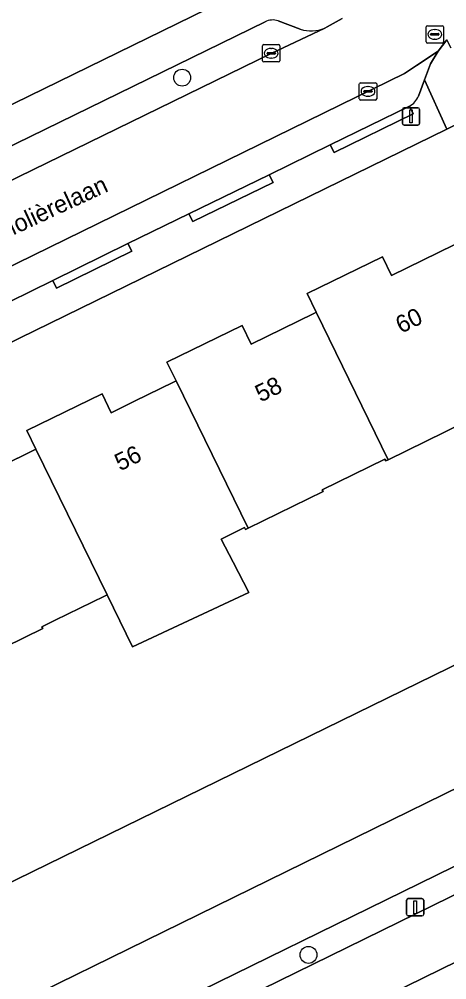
# Model space of a CAD drawing. Extents: x 160455 to 162082, y 388339 to 389736.
# Drawn here: x 160904.5 to 160929.1, y 388725.9 to 388781.3 of the extents above; entities that cross this region are included whole.
import ezdxf

# ---------------------------------------------------------------- set-up
doc = ezdxf.new("R2010")
doc.units = 0
for name, color, linetype in [('IMGEO_Boom', 7, 'Continuous'), ('IMGEO_Erf', 7, 'Continuous'), ('IMGEO_Fietspad_gesloten', 7, 'Continuous'), ('IMGEO_Groenvoorziening', 7, 'Continuous'), ('IMGEO_Haag', 7, 'Continuous'), ('IMGEO_Kolk', 7, 'Continuous'), ('IMGEO_Lichtmast', 7, 'Continuous'), ('IMGEO_Oever', 7, 'Continuous'), ('IMGEO_Openbare_ruimte_label', 7, 'Continuous'), ('IMGEO_Pand', 7, 'Continuous'), ('IMGEO_Pand_nummerreeks', 7, 'Continuous'), ('IMGEO_Parkeervlak_open', 7, 'Continuous'), ('IMGEO_Rijbaan_lokaal_gesloten', 7, 'Continuous'), ('IMGEO_Rioolput', 7, 'Continuous'), ('IMGEO_Voetpad_open', 7, 'Continuous'), ('IMGEO_Waterloop', 7, 'Continuous')]:
    doc.layers.add(name, color=color, linetype=linetype)

msp = doc.modelspace()

# ---------------------------------------------------------------- linework, layer by layer
at = {"layer": 'IMGEO_Boom'}
for centre in [(160913.862, 388777.923), (160921.145, 388727.384)]:
    msp.add_circle(centre, 0.489, dxfattribs=at)
at = {"layer": 'IMGEO_Erf'}
for points in [[(160875.947, 388762.656), (160922.127, 388785.223)], [(160937.925, 388772.412), (160936.05, 388776.299), (160935.249, 388777.96), (160929.117, 388774.962), (160878.066, 388750), (160811.085, 388717.249)], [(160903.479, 388755.554), (160905.278, 388756.436), (160905.432, 388756.511), (160904.905, 388757.589), (160909.244, 388759.7), (160909.769, 388758.621), (160911.113, 388759.28), (160913.365, 388760.383), (160913.506, 388760.452), (160912.979, 388761.53), (160917.319, 388763.649), (160917.846, 388762.57), (160919.648, 388763.453), (160921.449, 388764.335), (160921.596, 388764.407), (160921.07, 388765.485), (160925.406, 388767.601), (160925.932, 388766.523), (160927.736, 388767.405), (160929.539, 388768.286)], [(160766.298, 388664.267), (160941.708, 388750), (160948.921, 388753.525), (160948.021, 388755.303), (160947.977, 388755.282), (160946.576, 388758.143), (160949.559, 388759.604), (160949.905, 388758.897), (160955.447, 388761.62), (160953.756, 388765.074), (160956.812, 388766.571), (160958.502, 388763.122), (160958.774, 388763.255), (160957.453, 388765.953), (160960.515, 388767.453), (160961.835, 388764.759), (160968.352, 388767.962)], [(160930.077, 388758.031), (160925.745, 388755.914), (160925.595, 388755.841), (160925.543, 388755.949), (160921.932, 388754.184), (160921.985, 388754.076), (160917.66, 388751.963), (160917.512, 388751.891), (160917.46, 388751.998), (160916.111, 388751.339), (160916.803, 388750), (160917.703, 388748.259), (160910.996, 388745.13), (160909.532, 388748.124), (160909.385, 388748.052), (160906.545, 388746.665), (160905.775, 388746.288), (160905.828, 388746.18), (160901.5, 388744.065)]]:
    msp.add_lwpolyline(points, dxfattribs=at)
at = {"layer": 'IMGEO_Fietspad_gesloten'}
for points in [[(160976.671, 388750), (161000, 388761.421), (161006.396, 388764.552), (161005.803, 388768.175), (161001.6, 388766.116), (161000, 388765.333), (160968.696, 388750), (160830.802, 388682.457), (160825.311, 388679.157), (160825.396, 388678.948)], [(160835.236, 388680.785), (160877.263, 388701.324), (160886.716, 388705.962), (160976.671, 388750)]]:
    msp.add_lwpolyline(points, dxfattribs=at)
at = {"layer": 'IMGEO_Groenvoorziening'}
msp.add_lwpolyline([(160968.696, 388750), (161000, 388765.333), (161001.6, 388766.116), (161001.239, 388766.89), (161000.979, 388767.447), (160965.347, 388750), (160778.313, 388658.421), (160776.807, 388656.846), (160777.453, 388655.571), (160825.396, 388678.948), (160825.311, 388679.157), (160830.802, 388682.457)], close=True, dxfattribs=at)
at = {"layer": 'IMGEO_Haag'}
msp.add_lwpolyline([(160968.696, 388750), (161000, 388765.333), (161001.6, 388766.116), (161001.239, 388766.89), (161000.979, 388767.447), (160965.347, 388750), (160778.313, 388658.421), (160776.807, 388656.846), (160777.453, 388655.571), (160825.396, 388678.948), (160825.311, 388679.157), (160830.802, 388682.457)], close=True, dxfattribs=at)
at = {"layer": 'IMGEO_Kolk'}
for p, q in [((160918.494, 388778.9), (160918.494, 388779.752)), ((160918.569, 388779.826), (160919.421, 388779.826)), ((160919.495, 388779.752), (160919.495, 388778.9)), ((160918.753, 388779.32), (160918.753, 388779.332)), ((160919.191, 388779.283), (160918.793, 388779.283)), ((160918.796, 388779.369), (160919.194, 388779.369)), ((160918.982, 388779.606), (160919.007, 388779.606)), ((160919.237, 388779.332), (160919.237, 388779.32)), ((160919.421, 388778.826), (160918.569, 388778.826)), ((160919.005, 388779.046), (160918.98, 388779.046)), ((160924.075, 388776.706), (160924.075, 388777.558)), ((160924.15, 388777.632), (160925.002, 388777.632)), ((160925.076, 388777.558), (160925.076, 388776.706)), ((160924.334, 388777.126), (160924.334, 388777.138)), ((160924.772, 388777.089), (160924.374, 388777.089)), ((160924.377, 388777.175), (160924.775, 388777.175)), ((160924.563, 388777.412), (160924.588, 388777.412)), ((160924.818, 388777.138), (160924.818, 388777.126)), ((160925.002, 388776.632), (160924.15, 388776.632)), ((160924.586, 388776.852), (160924.561, 388776.852))]:
    msp.add_line(p, q, dxfattribs=at)
for points in [[(160918.494, 388778.9), (160918.494, 388779.752)], [(160918.569, 388779.826), (160919.421, 388779.826)], [(160919.495, 388779.752), (160919.495, 388778.9)], [(160919.421, 388778.826), (160918.569, 388778.826)], [(160924.075, 388776.706), (160924.075, 388777.558)], [(160924.15, 388777.632), (160925.002, 388777.632)], [(160925.076, 388777.558), (160925.076, 388776.706)], [(160925.002, 388776.632), (160924.15, 388776.632)]]:
    msp.add_lwpolyline(points, dxfattribs=at)
for centre, radius, start, end in [((160918.571, 388779.75), 0.0765, 91.552, 178.448), ((160918.571, 388779.75), 0.0765, 91.552, 178.448), ((160919.419, 388779.75), 0.0765, 1.552, 88.448), ((160919.419, 388779.75), 0.0765, 1.552, 88.448), ((160918.793, 388779.329), 0.0403, 85.8775, 175.7526), ((160918.79, 388779.319), 0.0366, 178.938, 274.7102), ((160919.194, 388779.326), 0.043, 264.8664, 352.4533), ((160919.198, 388779.331), 0.0386, 1.7309, 96.639), ((160918.571, 388778.902), 0.0765, 181.552, 268.448), ((160918.571, 388778.902), 0.0765, 181.552, 268.448), ((160919.419, 388778.902), 0.0765, 271.552, 358.448), ((160919.419, 388778.902), 0.0765, 271.552, 358.448), ((160924.152, 388777.556), 0.0765, 91.552, 178.448), ((160924.152, 388777.556), 0.0765, 91.552, 178.448), ((160925, 388777.556), 0.0765, 1.552, 88.448), ((160925, 388777.556), 0.0765, 1.552, 88.448), ((160924.374, 388777.135), 0.0403, 85.8775, 175.7526), ((160924.371, 388777.125), 0.0366, 178.938, 274.7102), ((160924.775, 388777.132), 0.043, 264.8664, 352.4533), ((160924.779, 388777.137), 0.0386, 1.7309, 96.639), ((160924.152, 388776.708), 0.0765, 181.552, 268.448), ((160924.152, 388776.708), 0.0765, 181.552, 268.448), ((160925, 388776.708), 0.0765, 271.552, 358.448), ((160925, 388776.708), 0.0765, 271.552, 358.448)]:
    msp.add_arc(centre, radius, start, end, dxfattribs=at)
for centre, major_axis, ratio, start_param, end_param in [((160918.981, 388779.326), (-0.387, 0.002), 0.722429, 4.712389, 7.853982), ((160919.006, 388779.326), (-0.39, 0.002), 0.717154, 1.570796, 4.712389), ((160924.562, 388777.132), (-0.387, 0.002), 0.722429, 4.712389, 7.853982), ((160924.587, 388777.132), (-0.39, 0.002), 0.717154, 1.570796, 4.712389)]:
    msp.add_ellipse(centre, major_axis=major_axis, ratio=ratio, start_param=start_param, end_param=end_param, dxfattribs=at)
at = {"layer": 'IMGEO_Lichtmast'}
for p, q in [((160926.56, 388775.291), (160926.56, 388776.091)), ((160926.56, 388776.091), (160926.56, 388775.291)), ((160926.66, 388776.191), (160927.45, 388776.191)), ((160927.45, 388776.191), (160926.66, 388776.191)), ((160927.55, 388776.091), (160927.55, 388775.291)), ((160927.55, 388775.291), (160927.55, 388776.091)), ((160927.45, 388775.191), (160926.66, 388775.191)), ((160926.66, 388775.191), (160927.45, 388775.191)), ((160926.795, 388729.731), (160926.795, 388730.531)), ((160926.795, 388730.531), (160926.795, 388729.731)), ((160926.895, 388730.631), (160927.685, 388730.631)), ((160927.685, 388730.631), (160926.895, 388730.631)), ((160927.785, 388730.531), (160927.785, 388729.731)), ((160927.785, 388729.731), (160927.785, 388730.531)), ((160927.685, 388729.631), (160926.895, 388729.631)), ((160926.895, 388729.631), (160927.685, 388729.631))]:
    msp.add_line(p, q, dxfattribs=at)
for points in [[(160926.98, 388776.066), (160927.13, 388776.066), (160927.13, 388775.316), (160926.98, 388775.316), (160926.98, 388776.066)], [(160927.215, 388730.506), (160927.365, 388730.506), (160927.365, 388729.756), (160927.215, 388729.756), (160927.215, 388730.506)]]:
    msp.add_lwpolyline(points, dxfattribs=at)
for centre, start, end in [((160926.66, 388776.091), 90, 180), ((160926.66, 388776.091), 90, 180), ((160927.45, 388776.091), 0, 90), ((160927.45, 388776.091), 360, 90), ((160926.66, 388775.291), 180, 270), ((160926.66, 388775.291), 180, 270), ((160927.45, 388775.291), 270, 0), ((160927.45, 388775.291), 270, 0), ((160926.895, 388730.531), 90, 180), ((160926.895, 388730.531), 90, 180), ((160927.685, 388730.531), 0, 90), ((160927.685, 388730.531), 360, 90), ((160926.895, 388729.731), 180, 270), ((160926.895, 388729.731), 180, 270), ((160927.685, 388729.731), 270, 0), ((160927.685, 388729.731), 270, 0)]:
    msp.add_arc(centre, 0.1, start, end, dxfattribs=at)
at = {"layer": 'IMGEO_Oever'}
msp.add_lwpolyline([(160965.347, 388750), (161000.979, 388767.447), (161004.923, 388771.881), (161004.47, 388772.822), (161004.366, 388772.775), (161004.045, 388773.679), (161000, 388771.638), (160986.989, 388765.073), (160956.23, 388750), (160783.435, 388665.323), (160769.08, 388658.493), (160770.196, 388656.176), (160776.807, 388656.846), (160778.313, 388658.421)], close=True, dxfattribs=at)
at = {"layer": 'IMGEO_Pand'}
for points in [[(160929.681, 388768.355), (160929.539, 388768.286), (160927.736, 388767.405), (160925.932, 388766.523), (160925.406, 388767.601), (160921.07, 388765.485), (160921.596, 388764.407), (160925.745, 388755.914), (160930.077, 388758.031), (160930.024, 388758.139), (160933.644, 388759.908), (160933.696, 388759.8), (160933.848, 388759.874)], [(160921.596, 388764.407), (160921.449, 388764.335), (160919.648, 388763.453), (160917.846, 388762.57), (160917.319, 388763.649), (160912.979, 388761.53), (160913.506, 388760.452), (160917.66, 388751.963), (160921.985, 388754.076), (160921.932, 388754.184), (160925.543, 388755.949), (160925.595, 388755.841), (160925.745, 388755.914)], [(160913.506, 388760.452), (160913.365, 388760.383), (160911.113, 388759.28), (160909.769, 388758.621), (160909.244, 388759.7), (160904.905, 388757.589), (160905.432, 388756.511), (160908.615, 388750), (160909.532, 388748.124), (160910.996, 388745.13), (160917.703, 388748.259), (160916.803, 388750), (160916.111, 388751.339), (160917.46, 388751.998), (160917.512, 388751.891), (160917.66, 388751.963)], [(160905.432, 388756.511), (160905.278, 388756.436), (160903.479, 388755.554), (160901.679, 388754.672), (160901.153, 388755.751), (160896.824, 388753.641), (160897.351, 388752.562), (160898.602, 388750), (160901.5, 388744.065), (160905.828, 388746.18), (160905.775, 388746.288), (160906.545, 388746.665), (160909.385, 388748.052), (160909.532, 388748.124), (160908.615, 388750)]]:
    msp.add_lwpolyline(points, close=True, dxfattribs=at)
at = {"layer": 'IMGEO_Parkeervlak_open'}
msp.add_lwpolyline([(160927.483, 388776.866), (160927.831, 388777.792), (160928.178, 388778.717), (160928.626, 388779.448), (160927.363, 388778.614), (160926.684, 388778.165), (160901.535, 388765.865), (160881.617, 388756.126), (160879.999, 388755.357), (160880.802, 388753.74), (160882.009, 388754.317), (160886.347, 388756.438), (160890.137, 388758.307), (160894.483, 388760.414), (160898.273, 388762.276), (160902.641, 388764.4), (160906.397, 388766.234), (160910.736, 388768.366), (160914.255, 388770.086), (160918.883, 388772.324), (160922.403, 388774.059), (160926.965, 388776.289)], dxfattribs=at)
msp.add_arc((160926.48, 388777.245), 1.072, 296.8767, 339.2917, dxfattribs=at)
at = {"layer": 'IMGEO_Rijbaan_lokaal_gesloten'}
msp.add_lwpolyline([(160923.089, 388781.332), (160922.221, 388780.848), (160922.077, 388780.78), (160918.996, 388779.324), (160899.56, 388769.847), (160880.511, 388760.545), (160877.968, 388759.28), (160879.999, 388755.357), (160881.617, 388756.126), (160901.535, 388765.865), (160926.684, 388778.165), (160927.363, 388778.614), (160928.626, 388779.448), (160929.119, 388780.101)], dxfattribs=at)
at = {"layer": 'IMGEO_Rioolput'}
for p, q in [((160927.925, 388779.991), (160927.925, 388780.843)), ((160928, 388780.917), (160928.852, 388780.917)), ((160928.926, 388780.843), (160928.926, 388779.991)), ((160928.184, 388780.411), (160928.184, 388780.423)), ((160928.622, 388780.374), (160928.224, 388780.374)), ((160928.227, 388780.46), (160928.625, 388780.46)), ((160928.413, 388780.697), (160928.438, 388780.697)), ((160928.668, 388780.423), (160928.668, 388780.411)), ((160928.852, 388779.917), (160928, 388779.917)), ((160928.436, 388780.137), (160928.411, 388780.137))]:
    msp.add_line(p, q, dxfattribs=at)
for points in [[(160927.925, 388779.991), (160927.925, 388780.843)], [(160928, 388780.917), (160928.852, 388780.917)], [(160928.926, 388780.843), (160928.926, 388779.991)], [(160928.852, 388779.917), (160928, 388779.917)]]:
    msp.add_lwpolyline(points, dxfattribs=at)
for centre, radius, start, end in [((160928.002, 388780.841), 0.0765, 91.552, 178.448), ((160928.002, 388780.841), 0.0765, 91.552, 178.448), ((160928.85, 388780.841), 0.0765, 1.552, 88.448), ((160928.85, 388780.841), 0.0765, 1.552, 88.448), ((160928.224, 388780.42), 0.0403, 85.8775, 175.7526), ((160928.221, 388780.41), 0.0366, 178.938, 274.7102), ((160928.625, 388780.417), 0.043, 264.8664, 352.4533), ((160928.629, 388780.422), 0.0386, 1.7309, 96.639), ((160928.002, 388779.993), 0.0765, 181.552, 268.448), ((160928.002, 388779.993), 0.0765, 181.552, 268.448), ((160928.85, 388779.993), 0.0765, 271.552, 358.448), ((160928.85, 388779.993), 0.0765, 271.552, 358.448)]:
    msp.add_arc(centre, radius, start, end, dxfattribs=at)
for centre, major_axis, ratio, start_param, end_param in [((160928.412, 388780.417), (-0.387, 0.002), 0.722429, 4.712389, 7.853982), ((160928.437, 388780.417), (-0.39, 0.002), 0.717154, 1.570796, 4.712389)]:
    msp.add_ellipse(centre, major_axis=major_axis, ratio=ratio, start_param=start_param, end_param=end_param, dxfattribs=at)
at = {"layer": 'IMGEO_Voetpad_open'}
for points in [[(160929.375, 388779.613), (160929.119, 388780.101), (160928.626, 388779.448), (160928.178, 388778.717), (160927.831, 388777.792), (160929.117, 388774.962), (160935.249, 388777.96), (160936.05, 388776.299), (160937.925, 388772.412), (160939.088, 388772.99), (160937.225, 388776.774), (160962.186, 388789.06)], [(160922.127, 388785.223), (160875.947, 388762.656), (160870.711, 388757.874)], [(160877.968, 388759.28), (160880.511, 388760.545), (160899.56, 388769.847), (160918.996, 388779.324), (160922.077, 388780.78)], [(160918.637, 388781.134), (160879.737, 388762.15)], [(160879.737, 388762.15), (160918.637, 388781.134)], [(160920.673, 388780.708), (160919.401, 388781.198)], [(160919.401, 388781.198), (160920.673, 388780.708)], [(160922.077, 388780.78), (160922.221, 388780.848), (160923.089, 388781.332)], [(160878.066, 388750), (160929.117, 388774.962), (160927.831, 388777.792), (160927.483, 388776.866)], [(160926.965, 388776.289), (160927.184, 388775.84), (160922.622, 388773.61), (160922.403, 388774.059), (160918.883, 388772.324), (160919.1, 388771.874), (160914.472, 388769.636), (160914.255, 388770.086), (160910.736, 388768.366), (160910.956, 388767.918), (160906.617, 388765.786), (160906.397, 388766.234), (160902.641, 388764.4)], [(160957.1, 388738.085), (160962.382, 388740.651), (160981.436, 388750), (161000, 388759.109), (161005.821, 388761.965), (161007.303, 388762.692), (161006.396, 388764.552), (161000, 388761.421), (160976.671, 388750), (160886.716, 388705.962)]]:
    msp.add_lwpolyline(points, dxfattribs=at)
for points in [[(160922.403, 388774.059), (160922.622, 388773.61), (160927.184, 388775.84), (160926.965, 388776.289)], [(160918.883, 388772.324), (160914.255, 388770.086), (160914.472, 388769.636), (160919.1, 388771.874)], [(160906.397, 388766.234), (160906.617, 388765.786), (160910.956, 388767.918), (160910.736, 388768.366)]]:
    msp.add_lwpolyline(points, close=True, dxfattribs=at)
for centre, radius, start, end in [((160919.093, 388780.282), 0.966, 71.4105, 118.1665), ((160919.093, 388780.282), 0.966, 71.4105, 118.1665), ((160921.277, 388782.653), 2.037, 252.7461, 293.1252), ((160921.277, 388782.653), 2.037, 252.7461, 293.1252), ((160926.48, 388777.245), 1.072, 296.8767, 339.2917)]:
    msp.add_arc(centre, radius, start, end, dxfattribs=at)
at = {"layer": 'IMGEO_Waterloop'}
msp.add_lwpolyline([(160956.23, 388750), (160986.989, 388765.073), (161000, 388771.638), (161004.045, 388773.679), (161001.348, 388779.301), (161000, 388778.665), (160998.756, 388778.042), (160985.165, 388771.24), (160948.921, 388753.525), (160941.708, 388750), (160766.298, 388664.267), (160769.08, 388658.493), (160783.435, 388665.323)], close=True, dxfattribs=at)

# ---------------------------------------------------------------- texts
at = {"layer": 'IMGEO_Openbare_ruimte_label'}
msp.add_text('Molièrelaan', height=1, rotation=24.8992, dxfattribs=at).set_placement((160903.398, 388768.493))
at = {"layer": 'IMGEO_Pand_nummerreeks'}
for s, p in [('60', (160926.48, 388763.162)), ('58', (160918.382, 388759.2)), ('56', (160910.281, 388755.237))]:
    msp.add_text(s, height=1, rotation=26.0696, dxfattribs=at).set_placement(p)

doc.saveas('drawing.dxf')
